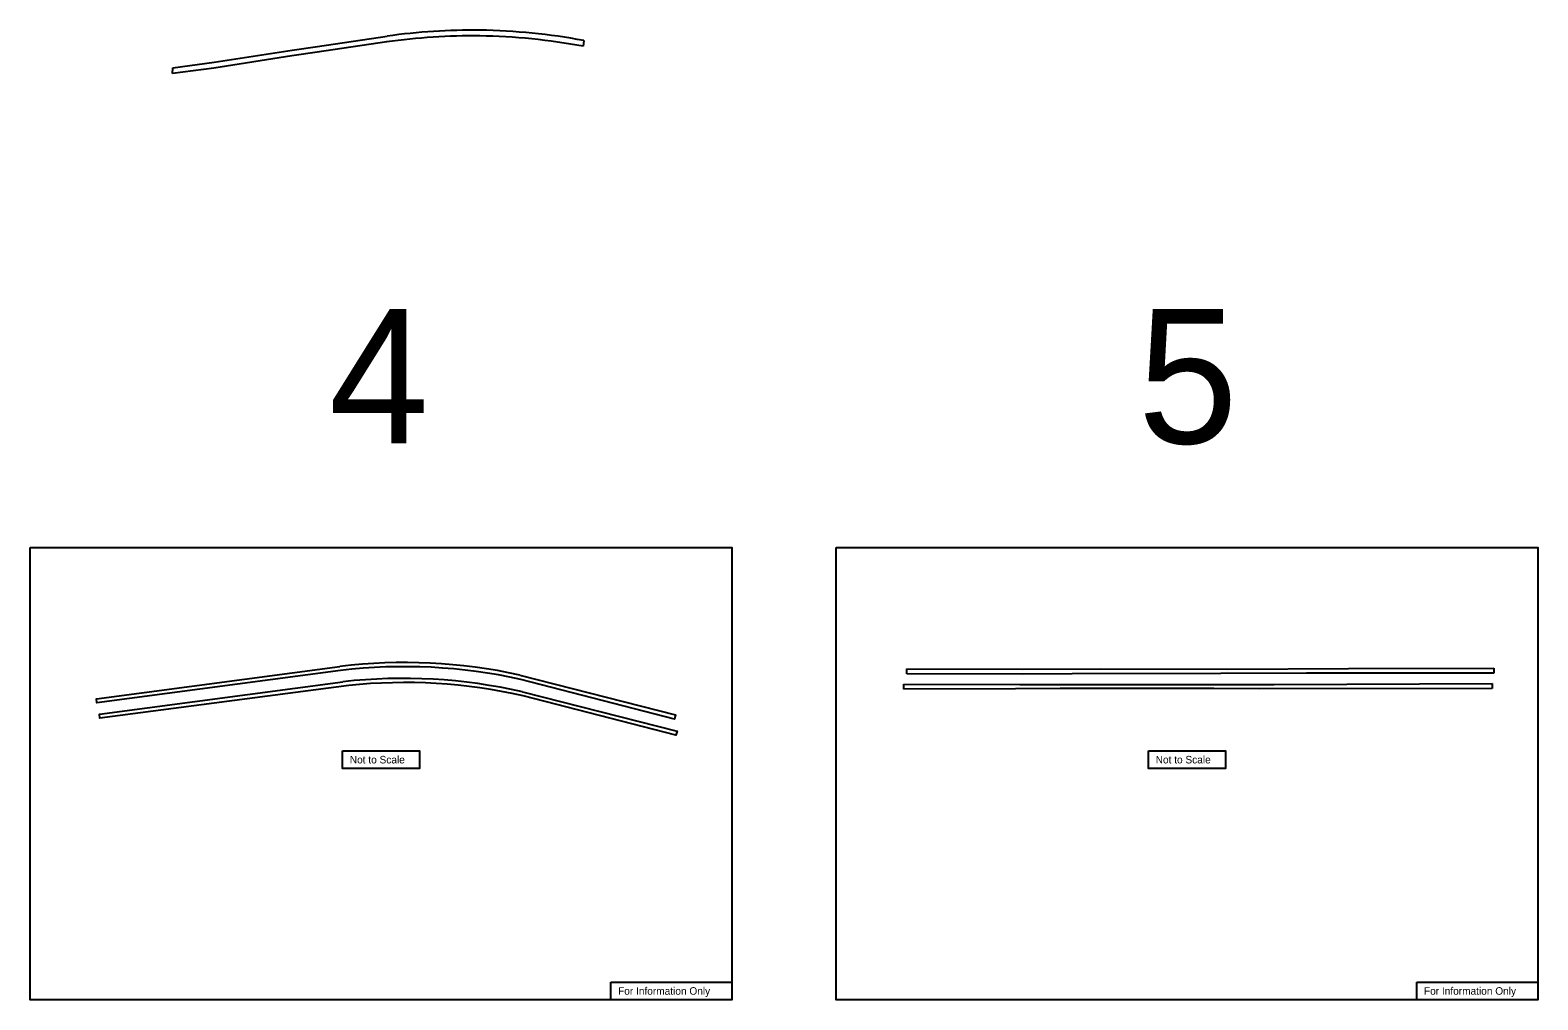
# Model space of a CAD drawing. Extents: x 10133 to 81668, y 7924 to 12255.
# Drawn here: x 20933 to 27668, y 7924 to 12255 of the extents above; entities that cross this region are included whole.
import ezdxf

# ---------------------------------------------------------------- set-up
doc = ezdxf.new("R2010")
doc.units = 0
for name, color, linetype in [('RasterAttachment', 7, 'Continuous'), ('SheetBorder', 7, 'Continuous'), ('SheetText', 7, 'Continuous')]:
    doc.layers.add(name, color=color, linetype=linetype)

msp = doc.modelspace()

# ---------------------------------------------------------------- linework, layer by layer
at = {"layer": 'RasterAttachment'}
for p, q in [((22525.1, 12203), (22214.7, 12156.4)), ((22216.6, 12182), (22527.1, 12228.6)), ((23405.4, 12208.9), (23403.5, 12183.2)), ((22101.6, 12139.8), (21752.8, 12086)), ((21754.7, 12111.6), (22103.5, 12165.4)), ((22214.7, 12156.4), (22101.6, 12139.8)), ((22103.5, 12165.4), (22216.6, 12182)), ((21568.3, 12061.9), (21570.2, 12087.5)), ((21752.8, 12086), (21568.3, 12061.9)), ((21570.2, 12087.5), (21754.7, 12111.6)), ((24849, 9379.8), (24849, 9402.1)), ((24849, 9402.1), (25367.5, 9400.3)), ((25367.5, 9378), (24849, 9379.8)), ((25367.5, 9400.3), (25715.8, 9402.1)), ((25587, 9380.8), (25367.5, 9378)), ((26250.7, 9381.4), (25587, 9380.8)), ((25715.8, 9402.1), (26281.7, 9400.8)), ((26633.8, 9382.7), (26250.7, 9381.4)), ((26281.7, 9400.8), (26821.6, 9403.4)), ((27470.8, 9383.5), (26633.8, 9382.7)), ((26821.6, 9403.4), (27470.8, 9405.8)), ((27470.8, 9405.8), (27470.8, 9383.5)), ((24835.1, 9312.2), (24835.1, 9334.5)), ((24835.1, 9334.5), (25353.6, 9332.7)), ((25333.8, 9313.8), (24835.1, 9312.2)), ((25533.2, 9314.3), (25333.8, 9313.8)), ((25353.6, 9332.7), (25542.5, 9332)), ((26220.3, 9314.6), (25533.2, 9314.3)), ((25542.5, 9332), (26265.6, 9332.9)), ((26425.8, 9313.9), (26220.3, 9314.6)), ((26265.6, 9332.9), (26489.9, 9332.4)), ((27464.1, 9315), (26425.8, 9313.9)), ((26489.9, 9332.4), (27464.1, 9337.2)), ((27464.1, 9337.2), (27464.1, 9315))]:
    msp.add_line(p, q, dxfattribs=at)
for points in [[(22319.5, 9395.3), (21230.6, 9251.1), (21228.6, 9269.1), (22316.1, 9413.1)], [(23119.4, 9374.8), (23815.6, 9196.3), (23810.9, 9178.2), (23124.9, 9355.2)], [(22355.5, 9327.9), (21244, 9182.6), (21242, 9200.6), (22329.5, 9344.6)], [(23131.4, 9299.4), (23822.1, 9123.5), (23817.4, 9105.8), (23134.4, 9281.6)]]:
    msp.add_lwpolyline(points, dxfattribs=at)
for centre, radius, start, end in [((22912, 9403.6), 2826, 89.41777, 97.86897), ((22914, 9429.2), 2826, 89.41777, 97.86897), ((22896.2, 9441.8), 2788, 79.51648, 89.08411), ((22898.1, 9467.4), 2788, 79.51648, 89.08411), ((22605.5, 7036.4), 2394.3, 77.60463, 96.94184), ((22604.5, 7012.1), 2400.1, 77.47897, 96.81958), ((22598.8, 6988.2), 2371.7, 77.02267, 96.51957), ((22606.2, 6970.8), 2370.4, 77.12586, 96.07217)]:
    msp.add_arc(centre, radius, start, end, dxfattribs=at)
at = {"layer": 'SheetBorder'}
for points in [[(20932.5, 9944), (24067.5, 9944), (24067.5, 7924), (20932.5, 7924)], [(24532.5, 9944), (27667.5, 9944), (27667.5, 7924), (24532.5, 7924)]]:
    msp.add_lwpolyline(points, close=True, dxfattribs=at)
at = {"layer": 'SheetText'}
for points in [[(22328.5, 9036.5), (22671.6, 9036.5), (22671.6, 8957.1), (22328.5, 8957.1)], [(25928.5, 9036.5), (26271.6, 9036.5), (26271.6, 8957.1), (25928.5, 8957.1)], [(23527, 8003.4), (24067.5, 8003.4), (24067.5, 7924), (23527, 7924)], [(27127, 8003.4), (27667.5, 8003.4), (27667.5, 7924), (27127, 7924)]]:
    msp.add_lwpolyline(points, close=True, dxfattribs=at)

# ---------------------------------------------------------------- texts
for s, height, p in [('4', 600, (22267.6, 10409.2)), ('5', 600, (25880.7, 10409.2)), ('Not to Scale', 33.75, (22360.4, 8979.9)), ('Not to Scale', 33.75, (25960.4, 8979.9)), ('For Information Only', 33.75, (23558.8, 7946.8)), ('For Information Only', 33.75, (27158.8, 7946.8))]:
    msp.add_text(s, height=height, dxfattribs=at).set_placement(p)

doc.saveas('drawing.dxf')
